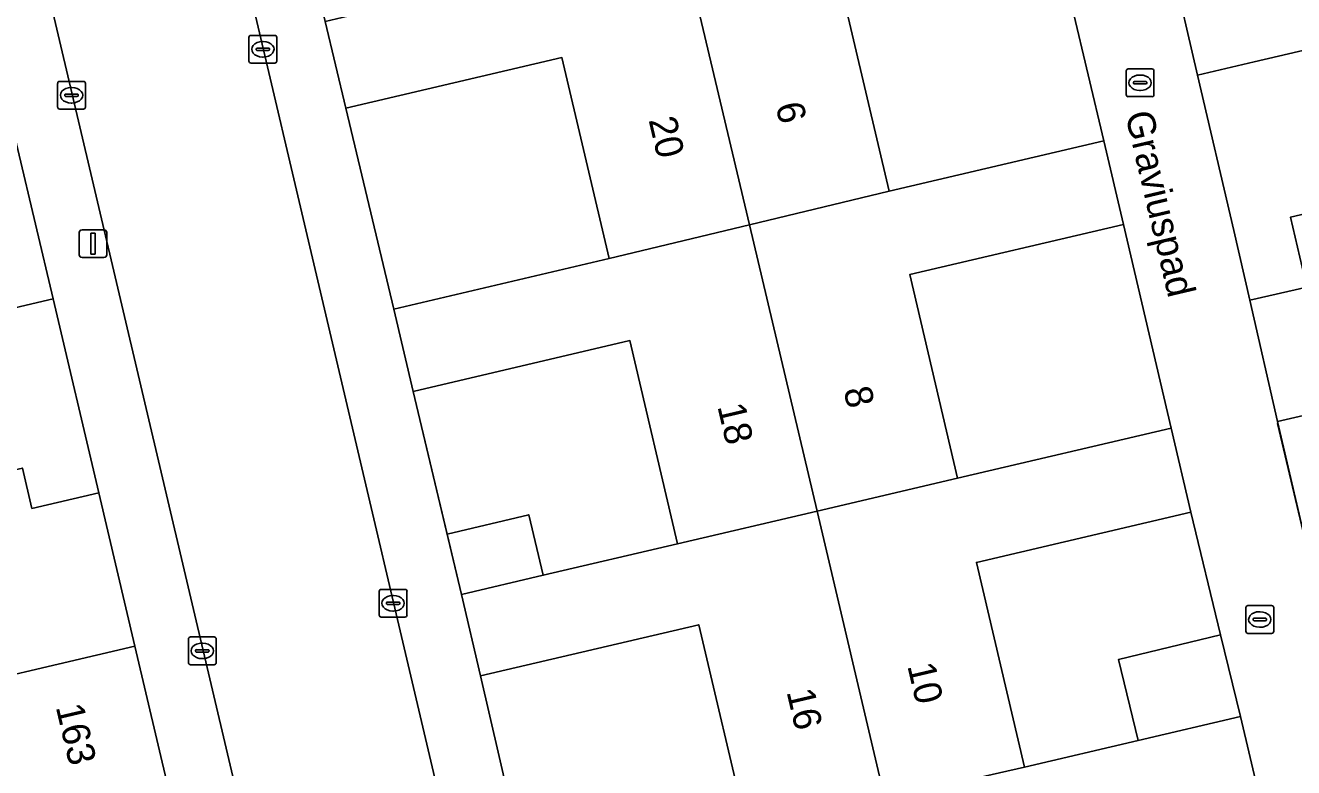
# Model space of a CAD drawing. Extents: x 162989 to 165008, y 383432 to 384338.
# Drawn here: x 164069.74 to 164115.4, y 384034.3 to 384061.03 of the extents above; entities that cross this region are included whole.
import ezdxf

# ---------------------------------------------------------------- set-up
doc = ezdxf.new("R2010")
doc.units = 0
for name, color, linetype in [('IMGEO_Erf', 7, 'Continuous'), ('IMGEO_Kolk', 7, 'Continuous'), ('IMGEO_Lichtmast', 7, 'Continuous'), ('IMGEO_Muur', 7, 'Continuous'), ('IMGEO_Openbare_ruimte_label', 7, 'Continuous'), ('IMGEO_Pand', 7, 'Continuous'), ('IMGEO_Pand_nummerreeks', 7, 'Continuous'), ('IMGEO_Rijbaan_lokaal_open', 7, 'Continuous'), ('IMGEO_Voetpad_open', 7, 'Continuous')]:
    doc.layers.add(name, color=color, linetype=linetype)

msp = doc.modelspace()

# ---------------------------------------------------------------- linework, layer by layer
at = {"layer": 'IMGEO_Erf'}
for points in [[(164106.872, 384064.013), (164099.158, 384062.203), (164100.834, 384055.065), (164108.562, 384056.879)], [(164121.686, 384060.895), (164116.233, 384059.62), (164116.095, 384060.211), (164113.972, 384059.715), (164111.942, 384059.24), (164113.243, 384053.645), (164113.821, 384051.131), (164115.871, 384051.609), (164115.284, 384054.122), (164122.855, 384055.891)], [(164083, 384050.811), (164090.756, 384052.632), (164089.056, 384059.875), (164081.27, 384058.048)], [(164069.463, 384056.565), (164067.068, 384056.003), (164066.718, 384057.495), (164061.053, 384056.165), (164062.667, 384049.287), (164070.743, 384051.183)], [(164109.269, 384053.864), (164101.58, 384052.06), (164103.302, 384044.726), (164110.99, 384046.531)], [(164114.823, 384046.77), (164116.11, 384041.219), (164116.828, 384038.156), (164117.738, 384034.267), (164119.11, 384028.412), (164122.003, 384029.088), (164124.896, 384029.764), (164127.789, 384030.44), (164128.995, 384030.722), (164127.312, 384037.927), (164121.826, 384036.646), (164122.141, 384035.296), (164119.787, 384034.746), (164118.885, 384038.609), (164118.164, 384041.695), (164120.404, 384042.232), (164125.795, 384043.522), (164124.19, 384050.393), (164118.793, 384049.132), (164119.112, 384047.766), (164116.891, 384047.247)], [(164091.503, 384049.68), (164083.696, 384047.848), (164084.919, 384042.705), (164087.863, 384043.405), (164088.381, 384041.229), (164093.22, 384042.365)], [(164072.383, 384044.2), (164069.974, 384043.634), (164069.632, 384045.09), (164063.953, 384043.757), (164065.592, 384036.777), (164073.683, 384038.676)], [(164112.77, 384039.086), (164111.701, 384043.503), (164103.981, 384041.691), (164105.712, 384034.315), (164109.805, 384035.276), (164109.098, 384038.197)], [(164087.843, 384030.19), (164095.721, 384032.04), (164093.984, 384039.443), (164086.125, 384037.599)]]:
    msp.add_lwpolyline(points, close=True, dxfattribs=at)
at = {"layer": 'IMGEO_Kolk'}
for p, q in [((164077.788, 384059.747), (164077.788, 384060.599)), ((164077.863, 384060.673), (164078.715, 384060.673)), ((164078.276, 384060.453), (164078.301, 384060.453)), ((164078.789, 384060.599), (164078.789, 384059.747)), ((164078.047, 384060.167), (164078.047, 384060.179)), ((164078.485, 384060.13), (164078.087, 384060.13)), ((164078.09, 384060.216), (164078.488, 384060.216)), ((164078.299, 384059.893), (164078.274, 384059.893)), ((164078.531, 384060.179), (164078.531, 384060.167)), ((164078.715, 384059.673), (164077.863, 384059.673)), ((164109.444, 384059.466), (164110.296, 384059.466)), ((164070.975, 384059.017), (164071.827, 384059.017)), ((164109.369, 384058.54), (164109.369, 384059.392)), ((164109.628, 384058.96), (164109.628, 384058.972)), ((164109.671, 384059.009), (164110.069, 384059.009)), ((164109.857, 384059.246), (164109.882, 384059.246)), ((164110.112, 384058.972), (164110.112, 384058.96)), ((164110.37, 384059.392), (164110.37, 384058.54)), ((164070.9, 384058.091), (164070.9, 384058.943)), ((164071.159, 384058.511), (164071.159, 384058.523)), ((164071.202, 384058.56), (164071.6, 384058.56)), ((164071.388, 384058.797), (164071.413, 384058.797)), ((164071.643, 384058.523), (164071.643, 384058.511)), ((164071.901, 384058.943), (164071.901, 384058.091)), ((164110.066, 384058.923), (164109.668, 384058.923)), ((164109.88, 384058.686), (164109.855, 384058.686)), ((164071.597, 384058.474), (164071.199, 384058.474)), ((164071.411, 384058.237), (164071.386, 384058.237)), ((164110.296, 384058.466), (164109.444, 384058.466)), ((164071.827, 384058.017), (164070.975, 384058.017)), ((164082.551, 384040.719), (164083.403, 384040.719)), ((164082.476, 384039.793), (164082.476, 384040.645)), ((164082.778, 384040.262), (164083.176, 384040.262)), ((164082.964, 384040.499), (164082.989, 384040.499)), ((164083.477, 384040.645), (164083.477, 384039.793)), ((164082.735, 384040.213), (164082.735, 384040.225)), ((164083.173, 384040.176), (164082.775, 384040.176)), ((164082.987, 384039.939), (164082.962, 384039.939)), ((164083.219, 384040.225), (164083.219, 384040.213)), ((164113.679, 384039.208), (164113.679, 384040.06)), ((164113.754, 384040.134), (164114.606, 384040.134)), ((164114.167, 384039.914), (164114.192, 384039.914)), ((164114.68, 384040.06), (164114.68, 384039.208)), ((164083.403, 384039.719), (164082.551, 384039.719)), ((164113.938, 384039.628), (164113.938, 384039.64)), ((164114.376, 384039.591), (164113.978, 384039.591)), ((164113.981, 384039.677), (164114.379, 384039.677)), ((164114.19, 384039.354), (164114.165, 384039.354)), ((164114.422, 384039.64), (164114.422, 384039.628)), ((164075.608, 384038.078), (164075.608, 384038.93)), ((164075.683, 384039.004), (164076.535, 384039.004)), ((164076.609, 384038.93), (164076.609, 384038.078)), ((164114.606, 384039.134), (164113.754, 384039.134)), ((164075.867, 384038.498), (164075.867, 384038.51)), ((164076.305, 384038.461), (164075.907, 384038.461)), ((164075.91, 384038.547), (164076.308, 384038.547)), ((164076.096, 384038.784), (164076.121, 384038.784)), ((164076.351, 384038.51), (164076.351, 384038.498)), ((164076.535, 384038.004), (164075.683, 384038.004)), ((164076.119, 384038.224), (164076.094, 384038.224))]:
    msp.add_line(p, q, dxfattribs=at)
for points in [[(164077.788, 384059.747), (164077.788, 384060.599)], [(164077.863, 384060.673), (164078.715, 384060.673)], [(164078.789, 384060.599), (164078.789, 384059.747)], [(164078.715, 384059.673), (164077.863, 384059.673)], [(164109.444, 384059.466), (164110.296, 384059.466)], [(164070.975, 384059.017), (164071.827, 384059.017)], [(164109.369, 384058.54), (164109.369, 384059.392)], [(164110.37, 384059.392), (164110.37, 384058.54)], [(164070.9, 384058.091), (164070.9, 384058.943)], [(164071.901, 384058.943), (164071.901, 384058.091)], [(164110.296, 384058.466), (164109.444, 384058.466)], [(164071.827, 384058.017), (164070.975, 384058.017)], [(164082.551, 384040.719), (164083.403, 384040.719)], [(164082.476, 384039.793), (164082.476, 384040.645)], [(164083.477, 384040.645), (164083.477, 384039.793)], [(164113.679, 384039.208), (164113.679, 384040.06)], [(164113.754, 384040.134), (164114.606, 384040.134)], [(164114.68, 384040.06), (164114.68, 384039.208)], [(164083.403, 384039.719), (164082.551, 384039.719)], [(164075.608, 384038.078), (164075.608, 384038.93)], [(164075.683, 384039.004), (164076.535, 384039.004)], [(164076.609, 384038.93), (164076.609, 384038.078)], [(164114.606, 384039.134), (164113.754, 384039.134)], [(164076.535, 384038.004), (164075.683, 384038.004)]]:
    msp.add_lwpolyline(points, dxfattribs=at)
for centre, radius, start, end in [((164077.865, 384060.597), 0.0765, 91.552, 178.448), ((164077.865, 384060.597), 0.0765, 91.552, 178.448), ((164078.713, 384060.597), 0.0765, 1.552, 88.448), ((164078.713, 384060.597), 0.0765, 1.552, 88.448), ((164078.087, 384060.176), 0.0403, 85.8775, 175.7526), ((164078.084, 384060.166), 0.0366, 178.938, 274.7102), ((164078.488, 384060.173), 0.043, 264.8664, 352.4533), ((164078.492, 384060.178), 0.0386, 1.7309, 96.639), ((164077.865, 384059.749), 0.0765, 181.552, 268.448), ((164077.865, 384059.749), 0.0765, 181.552, 268.448), ((164078.713, 384059.749), 0.0765, 271.552, 358.448), ((164078.713, 384059.749), 0.0765, 271.552, 358.448), ((164109.446, 384059.39), 0.0765, 91.552, 178.448), ((164109.446, 384059.39), 0.0765, 91.552, 178.448), ((164110.294, 384059.39), 0.0765, 1.552, 88.448), ((164110.294, 384059.39), 0.0765, 1.552, 88.448), ((164070.977, 384058.941), 0.0765, 91.552, 178.448), ((164070.977, 384058.941), 0.0765, 91.552, 178.448), ((164071.825, 384058.941), 0.0765, 1.552, 88.448), ((164071.825, 384058.941), 0.0765, 1.552, 88.448), ((164109.668, 384058.969), 0.0403, 85.8775, 175.7526), ((164110.073, 384058.971), 0.0386, 1.7309, 96.639), ((164071.199, 384058.52), 0.0403, 85.8775, 175.7526), ((164071.604, 384058.522), 0.0386, 1.7309, 96.639), ((164109.446, 384058.542), 0.0765, 181.552, 268.448), ((164109.446, 384058.542), 0.0765, 181.552, 268.448), ((164109.665, 384058.959), 0.0366, 178.938, 274.7102), ((164110.069, 384058.966), 0.043, 264.8664, 352.4533), ((164110.294, 384058.542), 0.0765, 271.552, 358.448), ((164110.294, 384058.542), 0.0765, 271.552, 358.448), ((164070.977, 384058.093), 0.0765, 181.552, 268.448), ((164070.977, 384058.093), 0.0765, 181.552, 268.448), ((164071.196, 384058.51), 0.0366, 178.938, 274.7102), ((164071.6, 384058.517), 0.043, 264.8664, 352.4533), ((164071.825, 384058.093), 0.0765, 271.552, 358.448), ((164071.825, 384058.093), 0.0765, 271.552, 358.448), ((164082.553, 384040.643), 0.0765, 91.552, 178.448), ((164082.553, 384040.643), 0.0765, 91.552, 178.448), ((164083.401, 384040.643), 0.0765, 1.552, 88.448), ((164083.401, 384040.643), 0.0765, 1.552, 88.448), ((164082.775, 384040.222), 0.0403, 85.8775, 175.7526), ((164083.18, 384040.224), 0.0386, 1.7309, 96.639), ((164082.772, 384040.212), 0.0366, 178.938, 274.7102), ((164083.176, 384040.219), 0.043, 264.8664, 352.4533), ((164113.756, 384040.058), 0.0765, 91.552, 178.448), ((164113.756, 384040.058), 0.0765, 91.552, 178.448), ((164114.604, 384040.058), 0.0765, 1.552, 88.448), ((164114.604, 384040.058), 0.0765, 1.552, 88.448), ((164082.553, 384039.795), 0.0765, 181.552, 268.448), ((164082.553, 384039.795), 0.0765, 181.552, 268.448), ((164083.401, 384039.795), 0.0765, 271.552, 358.448), ((164083.401, 384039.795), 0.0765, 271.552, 358.448), ((164113.978, 384039.637), 0.0403, 85.8775, 175.7526), ((164113.975, 384039.627), 0.0366, 178.938, 274.7102), ((164114.379, 384039.634), 0.043, 264.8664, 352.4533), ((164114.383, 384039.639), 0.0386, 1.7309, 96.639), ((164075.685, 384038.928), 0.0765, 91.552, 178.448), ((164075.685, 384038.928), 0.0765, 91.552, 178.448), ((164076.533, 384038.928), 0.0765, 1.552, 88.448), ((164076.533, 384038.928), 0.0765, 1.552, 88.448), ((164113.756, 384039.21), 0.0765, 181.552, 268.448), ((164113.756, 384039.21), 0.0765, 181.552, 268.448), ((164114.604, 384039.21), 0.0765, 271.552, 358.448), ((164114.604, 384039.21), 0.0765, 271.552, 358.448), ((164075.907, 384038.507), 0.0403, 85.8775, 175.7526), ((164075.904, 384038.497), 0.0366, 178.938, 274.7102), ((164076.308, 384038.504), 0.043, 264.8664, 352.4533), ((164076.312, 384038.509), 0.0386, 1.7309, 96.639), ((164075.685, 384038.08), 0.0765, 181.552, 268.448), ((164075.685, 384038.08), 0.0765, 181.552, 268.448), ((164076.533, 384038.08), 0.0765, 271.552, 358.448), ((164076.533, 384038.08), 0.0765, 271.552, 358.448)]:
    msp.add_arc(centre, radius, start, end, dxfattribs=at)
for centre, major_axis, ratio, start_param, end_param in [((164078.275, 384060.173), (-0.387, 0.002), 0.722429, 4.712389, 7.853982), ((164078.3, 384060.173), (-0.39, 0.002), 0.717154, 1.570796, 4.712389), ((164109.856, 384058.966), (-0.387, 0.002), 0.722429, 4.712389, 7.853982), ((164109.881, 384058.966), (-0.39, 0.002), 0.717154, 1.570796, 4.712389), ((164071.387, 384058.517), (-0.387, 0.002), 0.722429, 4.712389, 7.853982), ((164071.412, 384058.517), (-0.39, 0.002), 0.717154, 1.570796, 4.712389), ((164082.963, 384040.219), (-0.387, 0.002), 0.722429, 4.712389, 7.853982), ((164082.988, 384040.219), (-0.39, 0.002), 0.717154, 1.570796, 4.712389), ((164114.166, 384039.634), (-0.387, 0.002), 0.722429, 4.712389, 7.853982), ((164114.191, 384039.634), (-0.39, 0.002), 0.717154, 1.570796, 4.712389), ((164076.095, 384038.504), (-0.387, 0.002), 0.722429, 4.712389, 7.853982), ((164076.12, 384038.504), (-0.39, 0.002), 0.717154, 1.570796, 4.712389)]:
    msp.add_ellipse(centre, major_axis=major_axis, ratio=ratio, start_param=start_param, end_param=end_param, dxfattribs=at)
at = {"layer": 'IMGEO_Lichtmast'}
for p, q in [((164071.678, 384052.771), (164071.678, 384053.571)), ((164071.678, 384053.571), (164071.678, 384052.771)), ((164071.778, 384053.671), (164072.568, 384053.671)), ((164072.568, 384053.671), (164071.778, 384053.671)), ((164072.668, 384053.571), (164072.668, 384052.771)), ((164072.668, 384052.771), (164072.668, 384053.571)), ((164072.568, 384052.671), (164071.778, 384052.671)), ((164071.778, 384052.671), (164072.568, 384052.671))]:
    msp.add_line(p, q, dxfattribs=at)
msp.add_lwpolyline([(164072.098, 384053.546), (164072.248, 384053.546), (164072.248, 384052.796), (164072.098, 384052.796), (164072.098, 384053.546)], dxfattribs=at)
for centre, start, end in [((164071.778, 384053.571), 90, 180), ((164071.778, 384053.571), 90, 180), ((164072.568, 384053.571), 0, 90), ((164072.568, 384053.571), 360, 90), ((164071.778, 384052.771), 180, 270), ((164071.778, 384052.771), 180, 270), ((164072.568, 384052.771), 270, 0), ((164072.568, 384052.771), 270, 0)]:
    msp.add_arc(centre, 0.1, start, end, dxfattribs=at)
at = {"layer": 'IMGEO_Muur'}
for points in [[(164113.243, 384053.645), (164111.942, 384059.24)], [(164085.435, 384040.537), (164083.696, 384047.848)], [(164114.814, 384046.693), (164116.11, 384041.219)], [(164072.383, 384044.2), (164073.683, 384038.676)]]:
    msp.add_lwpolyline(points, dxfattribs=at)
at = {"layer": 'IMGEO_Pand'}
for points in [[(164128.702, 384057.372), (164125.73, 384069.816), (164123.854, 384069.338), (164118.23, 384067.907), (164112.377, 384066.539), (164113.039, 384063.707), (164111.013, 384063.235), (164111.942, 384059.24), (164113.972, 384059.715), (164116.095, 384060.211), (164116.233, 384059.62), (164121.686, 384060.895), (164122.855, 384055.891)], [(164100.834, 384055.065), (164099.158, 384062.203), (164106.872, 384064.013), (164106.129, 384067.179), (164098.422, 384065.371), (164093.366, 384064.184), (164095.805, 384053.85)], [(164093.366, 384064.184), (164088.342, 384063.006), (164081.965, 384061.509), (164080.537, 384061.174), (164081.27, 384058.048), (164089.056, 384059.875), (164090.756, 384052.632), (164095.805, 384053.85)], [(164128.702, 384057.372), (164122.855, 384055.891), (164115.284, 384054.122), (164115.871, 384051.609), (164113.821, 384051.131), (164114.823, 384046.77), (164116.891, 384047.247), (164119.112, 384047.766), (164118.793, 384049.132), (164124.19, 384050.393), (164125.795, 384043.522), (164131.673, 384044.93)], [(164098.239, 384043.54), (164103.302, 384044.726), (164101.58, 384052.06), (164109.269, 384053.864), (164108.562, 384056.879), (164100.834, 384055.065), (164095.805, 384053.85)], [(164093.22, 384042.365), (164098.239, 384043.54), (164095.805, 384053.85), (164090.756, 384052.632), (164083, 384050.811), (164083.696, 384047.848), (164091.503, 384049.68)], [(164057.123, 384047.982), (164057.178, 384047.747), (164058.74, 384041.105), (164060.064, 384035.478), (164065.592, 384036.777), (164063.953, 384043.757), (164069.632, 384045.09), (164069.974, 384043.634), (164072.383, 384044.2), (164070.743, 384051.183), (164062.667, 384049.287)], [(164098.239, 384043.54), (164100.686, 384033.171), (164105.712, 384034.315), (164103.981, 384041.691), (164111.701, 384043.503), (164110.99, 384046.531), (164103.302, 384044.726)], [(164098.239, 384043.54), (164093.22, 384042.365), (164088.381, 384041.229), (164085.435, 384040.537), (164086.125, 384037.599), (164093.984, 384039.443), (164095.721, 384032.04), (164100.686, 384033.171)], [(164084.919, 384042.705), (164085.435, 384040.537), (164088.381, 384041.229), (164087.863, 384043.405)], [(164112.77, 384039.086), (164109.098, 384038.197), (164109.805, 384035.276), (164113.483, 384036.139)], [(164060.064, 384035.478), (164060.868, 384032.058), (164061.692, 384028.555), (164063, 384022.993), (164068.548, 384024.295), (164066.88, 384031.397), (164072.521, 384032.721), (164072.883, 384031.179), (164075.309, 384031.749), (164073.683, 384038.676), (164065.592, 384036.777)], [(164106.432, 384031.369), (164114.176, 384033.187), (164113.483, 384036.139), (164109.805, 384035.276), (164105.712, 384034.315), (164100.686, 384033.171), (164103.18, 384022.605), (164108.212, 384023.786)]]:
    msp.add_lwpolyline(points, close=True, dxfattribs=at)
at = {"layer": 'IMGEO_Rijbaan_lokaal_open'}
for points in [[(164088.073, 384018.66), (164073.518, 384080.529)], [(164066.673, 384078.703), (164081.207, 384017.007)]]:
    msp.add_lwpolyline(points, dxfattribs=at)
at = {"layer": 'IMGEO_Voetpad_open'}
for points in [[(164116.11, 384041.219), (164114.823, 384046.77), (164113.821, 384051.131), (164113.243, 384053.645), (164111.942, 384059.24), (164111.013, 384063.235), (164109.064, 384071.616), (164107.424, 384078.635), (164106.171, 384084.104), (164105.059, 384088.862), (164101.219, 384087.962), (164103.09, 384080.205), (164103.757, 384077.362), (164104.424, 384074.522), (164106.129, 384067.179), (164106.872, 384064.013), (164108.562, 384056.879), (164109.269, 384053.864), (164110.99, 384046.531), (164111.701, 384043.503), (164112.77, 384039.086), (164113.483, 384036.139), (164114.176, 384033.187), (164116.605, 384023.106)], [(164083, 384050.811), (164081.27, 384058.048), (164080.537, 384061.174), (164078.843, 384068.454), (164078.17, 384071.322), (164077.496, 384074.192), (164075.66, 384081.971), (164073.518, 384080.529), (164088.073, 384018.66)], [(164063.922, 384079.957), (164064.148, 384078.972), (164064.824, 384076.093), (164066.473, 384069.071), (164067.816, 384063.58), (164069.463, 384056.565), (164070.743, 384051.183), (164072.383, 384044.2), (164073.683, 384038.676), (164075.309, 384031.749), (164076.628, 384026.192), (164077.951, 384020.558), (164079.574, 384013.63), (164081.313, 384006.451), (164091.409, 384002.913), (164093.474, 384003.388), (164097.152, 384004.269), (164104.901, 384006.108)], [(164081.207, 384017.007), (164066.673, 384078.703)], [(164090.199, 384019.761), (164088.545, 384027.198), (164087.843, 384030.19), (164086.125, 384037.599), (164085.435, 384040.537), (164084.919, 384042.705), (164083.696, 384047.848), (164083, 384050.811)]]:
    msp.add_lwpolyline(points, dxfattribs=at)

# ---------------------------------------------------------------- texts
at = {"layer": 'IMGEO_Openbare_ruimte_label'}
msp.add_text('Graviuspad', height=1, rotation=283.2438, dxfattribs=at).set_placement((164109.331, 384057.831))
at = {"layer": 'IMGEO_Pand_nummerreeks'}
for s, rotation, p in [('6', 283.2137, (164096.74, 384058.152)), ('20', 283.2065, (164092.171, 384057.631)), ('8', 283.2135, (164099.186, 384047.907)), ('18', 283.2078, (164094.648, 384047.312)), ('10', 283.2072, (164101.486, 384037.967)), ('16', 283.2007, (164097.138, 384037.032)), ('163', 283.2101, (164070.828, 384036.487))]:
    msp.add_text(s, height=1, rotation=rotation, dxfattribs=at).set_placement(p)

doc.saveas('drawing.dxf')
